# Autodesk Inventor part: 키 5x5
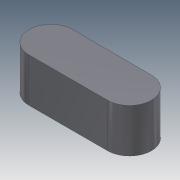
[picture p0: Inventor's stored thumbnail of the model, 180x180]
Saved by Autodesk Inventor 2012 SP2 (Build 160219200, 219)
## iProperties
Company: 한국ATC센터
Created: 2014-10
Part Number: 키 5x5
Document SubType Name: Modeling
Designer: KYOUNG IL JANG
Density: 1 g/cm^3
Mass: 0.323175 g
Surface Area: 2.9781 cm^2
Volume: 0.323175 cm^3
Material: 기본값
Author: KYOUNG IL JANG
Revision Number: 1
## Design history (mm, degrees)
sketch "스케치1"
  geometry: L1 (-4.5, -2.5)-(4.5, -2.5); L2 (4.5, 2.5)-(-4.5, 2.5); A1 r 2.5 centre (4.5, 0) between (4.5, -2.5) and (4.5, 2.5); A2 r 2.5 centre (-4.5, 0) between (-4.5, 2.5) and (-4.5, -2.5); 2 further points
  constraints: 4 end point, 4 point on circle, 4 tangent, 2 centre point, 1 horizontal, 1 horizontal alignment, 1 midpoint, 1 parallel, 1 vertical alignment
  dimensions: "d0" = 5 distance between parallel lines of L1 L2; "d1" = 14 dimension on A1 A2
extrude "돌출1" new body sketch "스케치1" stored distance "d2" = 5; taper "d3" = 0 deg
node "솔리드1"
